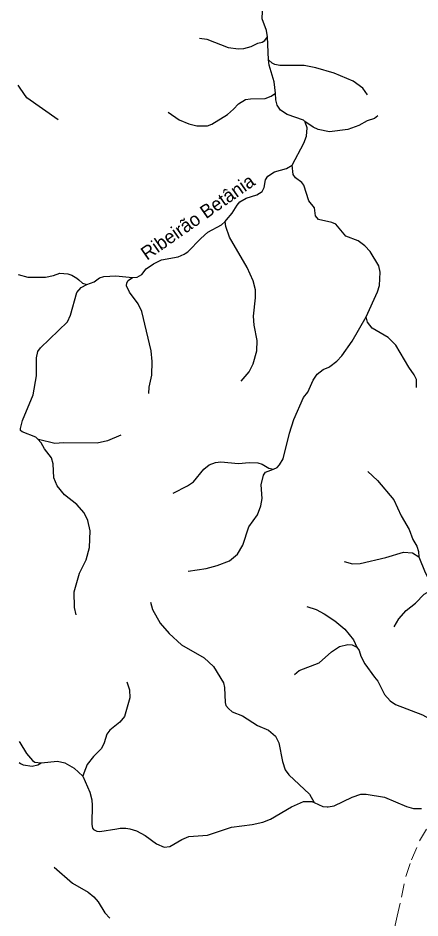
# Model space of a CAD drawing. Extents: x 473.9 to 500, y 7733.1 to 7760.8.
# Drawn here: x 473.9 to 476.88, y 7748.41 to 7755.08 of the extents above; entities that cross this region are included whole.
import ezdxf
from ezdxf.enums import TextEntityAlignment as Align

# ---------------------------------------------------------------- set-up
doc = ezdxf.new("R2010")
doc.units = 0
doc.header["$LTSCALE"] = 0.032
doc.linetypes.add('SHORT_DASHED', pattern=[2.7, 1.5, -1.2])
doc.layers.add('21', color=7, linetype='SHORT_DASHED', lineweight=13)
doc.layers.add('7', color=7, linetype='Continuous', lineweight=25)
doc.layers.add('61', color=7, linetype='Continuous')

msp = doc.modelspace()

# ---------------------------------------------------------------- linework, layer by layer
at = {"layer": '21'}
msp.add_lwpolyline([(476.688, 7748.3322), (476.7061, 7748.4194), (476.7376, 7748.5617), (476.7719, 7748.7144), (476.812, 7748.8386), (476.8731, 7748.9789), (476.9333, 7749.0811), (476.9689, 7749.1188), (477.0449, 7749.1653), (477.1611, 7749.2054), (477.4104, 7749.2751), (477.5096, 7749.3174), (477.554, 7749.3533), (477.5899, 7749.3913), (477.6275, 7749.4709)], dxfattribs=at)
at = {"layer": '7'}
msp.add_line((475.7531, 7754.7692), (475.7461, 7754.939), dxfattribs=at)
for points in [[(475.7461, 7754.939), (475.7396, 7754.9869), (475.7069, 7755.0721), (475.7082, 7755.1289), (475.6703, 7755.2102)], [(475.2436, 7754.9292), (475.2958, 7754.9229), (475.4549, 7754.8614), (475.5305, 7754.8493), (475.5716, 7754.8528), (475.6253, 7754.8675), (475.6747, 7754.8922), (475.7079, 7754.8999), (475.7267, 7754.9117), (475.7461, 7754.939)], [(475.8059, 7754.5227), (475.7959, 7754.6068), (475.7594, 7754.7284), (475.7531, 7754.7692)], [(476.488, 7754.5093), (476.4521, 7754.5578), (476.3815, 7754.6101), (476.239, 7754.6692), (476.105, 7754.7098), (476.0174, 7754.7273), (475.8385, 7754.7274), (475.8017, 7754.7336), (475.7806, 7754.7438), (475.7531, 7754.7692)], [(474.1951, 7754.3247), (473.964, 7754.488), (473.9141, 7754.5583), (473.8985, 7754.5803)], [(475.0106, 7754.3805), (475.0925, 7754.3229), (475.1646, 7754.294), (475.2231, 7754.2784), (475.3024, 7754.2798), (475.3348, 7754.2911), (475.4489, 7754.3627), (475.4952, 7754.4027), (475.5302, 7754.4424), (475.5829, 7754.4741), (475.6204, 7754.4804), (475.729, 7754.4826), (475.7744, 7754.4993), (475.8059, 7754.5227)], [(476.0222, 7754.3109), (476.013, 7754.3219), (475.8925, 7754.3625), (475.8421, 7754.3957), (475.8181, 7754.4336), (475.8088, 7754.4721), (475.8059, 7754.5227)], [(476.564, 7754.3546), (476.5382, 7754.3341), (476.4853, 7754.3168), (476.4233, 7754.2823), (476.341, 7754.252), (476.2048, 7754.2345), (476.1221, 7754.2517), (476.0852, 7754.2686), (476.0222, 7754.3109)], [(475.9288, 7753.987), (476.016, 7754.1513), (476.0343, 7754.2033), (476.0395, 7754.2655), (476.0264, 7754.306), (476.0222, 7754.3109)], [(475.4332, 7753.5703), (475.443, 7753.5824), (475.4834, 7753.6327), (475.5204, 7753.6925), (475.5425, 7753.7153), (475.5874, 7753.7437), (475.6665, 7753.7679), (475.7058, 7753.7925), (475.7205, 7753.8216), (475.7321, 7753.8802), (475.7499, 7753.9076), (475.7974, 7753.9384), (475.8879, 7753.9635), (475.9288, 7753.987)], [(476.4779, 7752.8624), (476.5616, 7753.0487), (476.5752, 7753.0969), (476.5815, 7753.1946), (476.5707, 7753.2415), (476.506, 7753.3486), (476.4672, 7753.389), (476.4174, 7753.4273), (476.3261, 7753.4618), (476.2527, 7753.5504), (476.2237, 7753.5633), (476.1233, 7753.5852), (476.1006, 7753.6129), (476.0938, 7753.6712), (476.0511, 7753.7229), (476.0147, 7753.839), (475.9993, 7753.8584), (475.953, 7753.8942), (475.9354, 7753.918), (475.9288, 7753.987)], [(474.7472, 7753.1562), (474.78, 7753.1585), (474.815, 7753.1782), (474.8483, 7753.2192), (474.9017, 7753.2571), (474.9617, 7753.2872), (475.0836, 7753.3086), (475.1293, 7753.3273), (475.1371, 7753.3326), (475.1574, 7753.3465), (475.252, 7753.4451), (475.3045, 7753.4907), (475.4048, 7753.5462), (475.4332, 7753.5703)], [(475.5511, 7752.3876), (475.6113, 7752.4549), (475.64, 7752.5152), (475.666, 7752.6113), (475.6707, 7752.6882), (475.6484, 7752.8012), (475.6428, 7752.8677), (475.6572, 7753.0039), (475.6572, 7753.0642), (475.6407, 7753.1308), (475.5953, 7753.2283), (475.4646, 7753.4544), (475.4367, 7753.5324), (475.4332, 7753.5703)], [(473.9006, 7753.1772), (473.9711, 7753.1568), (474.1027, 7753.1576), (474.1613, 7753.1691), (474.2083, 7753.1863), (474.2676, 7753.1815), (474.2968, 7753.1718), (474.3353, 7753.15), (474.3484, 7753.1385), (474.3768, 7753.1135), (474.408, 7753.1022)], [(474.408, 7753.1022), (474.4615, 7753.1221), (474.5031, 7753.1517), (474.5351, 7753.1615), (474.6226, 7753.168), (474.7472, 7753.1562)], [(474.8665, 7752.2962), (474.869, 7752.3416), (474.8906, 7752.4305), (474.8915, 7752.5314), (474.8834, 7752.6107), (474.8155, 7752.902), (474.789, 7752.96), (474.724, 7753.0458), (474.7024, 7753.0939), (474.7039, 7753.1146), (474.7144, 7753.1333), (474.7472, 7753.1562)], [(474.0454, 7751.9557), (474.0292, 7751.9725), (473.9296, 7752.0116), (473.918, 7752.0197), (473.9177, 7752.0363), (473.9323, 7752.0953), (474.0119, 7752.2855), (474.0359, 7752.4259), (474.0345, 7752.5587), (474.0446, 7752.6055), (474.0644, 7752.6344), (474.2652, 7752.8259), (474.2884, 7752.8765), (474.3352, 7753.0439), (474.3658, 7753.0822), (474.408, 7753.1022)], [(475.7901, 7751.7345), (475.8168, 7751.7471), (475.8358, 7751.7655), (475.8632, 7751.8105), (475.9099, 7752.002), (475.9415, 7752.1017), (476.0136, 7752.2643), (476.0446, 7752.3047), (476.0841, 7752.3936), (476.1142, 7752.4391), (476.1588, 7752.4723), (476.2008, 7752.4913), (476.2082, 7752.4946), (476.2595, 7752.5341), (476.2963, 7752.5733), (476.3739, 7752.6829), (476.4779, 7752.8624)], [(476.8506, 7752.3408), (476.8485, 7752.3982), (476.8324, 7752.4345), (476.7929, 7752.49), (476.6962, 7752.654), (476.6396, 7752.7092), (476.5205, 7752.7792), (476.486, 7752.824), (476.4779, 7752.8624)], [(474.6596, 7751.9852), (474.5618, 7751.945), (474.4858, 7751.927), (474.2363, 7751.9296), (474.1704, 7751.925), (474.0492, 7751.9548), (474.0454, 7751.9557)], [(474.3297, 7750.6537), (474.3158, 7750.7079), (474.3155, 7750.8248), (474.3531, 7750.9622), (474.4037, 7751.061), (474.4289, 7751.1537), (474.4328, 7751.2765), (474.4155, 7751.354), (474.3883, 7751.4106), (474.3345, 7751.471), (474.2421, 7751.5442), (474.1889, 7751.6116), (474.1632, 7751.6689), (474.1586, 7751.7739), (474.1474, 7751.8183), (474.094, 7751.8841), (474.0698, 7751.9305), (474.0454, 7751.9557)], [(475.0468, 7751.5549), (475.1549, 7751.6107), (475.1982, 7751.6401), (475.2736, 7751.7333), (475.3147, 7751.7656), (475.3615, 7751.7833), (475.4016, 7751.7896), (475.5317, 7751.776), (475.6092, 7751.784), (475.6739, 7751.7816), (475.707, 7751.77), (475.7555, 7751.7425), (475.7901, 7751.7345)], [(475.1584, 7750.9788), (475.2913, 7750.9973), (475.3736, 7751.0195), (475.4658, 7751.0546), (475.5236, 7751.1027), (475.5631, 7751.1717), (475.609, 7751.307), (475.6723, 7751.396), (475.6977, 7751.4631), (475.7069, 7751.5155), (475.6997, 7751.6187), (475.7166, 7751.6891), (475.7308, 7751.7108), (475.7901, 7751.7345)], [(476.4892, 7751.718), (476.5617, 7751.6491), (476.6826, 7751.5058), (476.7362, 7751.389), (476.7958, 7751.2858), (476.8235, 7751.2127), (476.852, 7751.162), (476.8653, 7751.1248), (476.8676, 7751.0851)], [(476.3135, 7751.0495), (476.3763, 7751.0311), (476.4321, 7751.0335), (476.6226, 7751.0786), (476.7542, 7751.1193), (476.8192, 7751.1139), (476.8676, 7751.0851)], [(476.8676, 7751.0851), (476.914, 7750.9677), (476.9479, 7750.9032), (476.9897, 7750.8554)], [(476.6842, 7750.5651), (476.7179, 7750.6238), (476.7738, 7750.6854), (476.8413, 7750.7418), (476.9068, 7750.8069), (476.9897, 7750.8554)], [(474.8789, 7750.7481), (474.8942, 7750.6937), (474.9511, 7750.5912), (475.0168, 7750.5146), (475.1094, 7750.4326), (475.2782, 7750.335), (475.3474, 7750.2705), (475.4194, 7750.1497), (475.4271, 7750.1164), (475.4327, 7750.0046), (475.4384, 7749.9822), (475.4562, 7749.9597), (475.4834, 7749.9358), (475.562, 7749.9045), (475.6714, 7749.8339), (475.7525, 7749.7988), (475.8065, 7749.7537), (475.8299, 7749.7039), (475.8569, 7749.5665), (475.8775, 7749.504), (475.9048, 7749.4677), (476.0564, 7749.3251), (476.0917, 7749.2639)], [(476.0369, 7750.7169), (476.1056, 7750.6927), (476.1659, 7750.6613), (476.2443, 7750.61), (476.318, 7750.5475), (476.3833, 7750.4686), (476.4075, 7750.4134)], [(475.9462, 7750.2128), (475.98, 7750.242), (476.129, 7750.2991), (476.2194, 7750.3787), (476.2801, 7750.4186), (476.3421, 7750.433), (476.3742, 7750.4307), (476.4075, 7750.4134)], [(476.4075, 7750.4134), (476.4239, 7750.3892), (476.4375, 7750.3474), (476.467, 7750.2904), (476.5392, 7750.1926), (476.5622, 7750.1615), (476.6132, 7750.0627), (476.6535, 7750.0157), (476.6933, 7749.9891), (476.8936, 7749.9129), (476.9385, 7749.889), (477.0156, 7749.8307), (477.0689, 7749.7713), (477.0708, 7749.7683), (477.1668, 7749.62), (477.2475, 7749.4731), (477.2754, 7749.4402), (477.3213, 7749.4148), (477.3441, 7749.4173), (477.3739, 7749.4339), (477.4269, 7749.4809), (477.4592, 7749.4997), (477.5049, 7749.5012)], [(474.7045, 7750.1572), (474.723, 7750.0979), (474.7262, 7750.0399), (474.6868, 7749.9003), (474.6535, 7749.8575), (474.5793, 7749.7993), (474.5556, 7749.7686), (474.536, 7749.7059), (474.5158, 7749.664), (474.4574, 7749.6045), (474.4105, 7749.5449), (474.3866, 7749.4808), (474.3785, 7749.4591)], [(473.9059, 7749.7157), (473.9108, 7749.7077), (473.9604, 7749.627), (474.005, 7749.5748), (474.0226, 7749.562), (474.069, 7749.556)], [(473.9061, 7749.5586), (473.9172, 7749.5523), (473.9361, 7749.5415), (474.0045, 7749.5318), (474.0463, 7749.5423), (474.069, 7749.556)], [(474.069, 7749.556), (474.1898, 7749.5688), (474.2457, 7749.5579), (474.3139, 7749.5184), (474.3785, 7749.4591)], [(474.3785, 7749.4591), (474.4294, 7749.3384), (474.4448, 7749.2817), (474.4459, 7749.2731), (474.4488, 7749.2502), (474.4449, 7749.0999), (474.4505, 7749.0712), (474.4587, 7749.0619), (474.4812, 7749.0503), (474.5045, 7749.0483), (474.6306, 7749.0678), (474.6551, 7749.0716), (474.6961, 7749.0732), (474.7278, 7749.0676), (474.7765, 7749.0521), (474.8401, 7749.0179), (474.9233, 7748.9574), (474.98, 7748.9326), (475.022, 7748.9365), (475.1109, 7748.9889), (475.1627, 7749.0115), (475.3025, 7749.0217), (475.4802, 7749.0797), (475.6322, 7749.0988), (475.7118, 7749.1172), (475.7688, 7749.1399), (475.9247, 7749.2302), (476.013, 7749.2692), (476.0754, 7749.2693), (476.0917, 7749.2639)], [(476.0917, 7749.2639), (476.1548, 7749.2331), (476.1876, 7749.2304), (476.1955, 7749.2315), (476.2407, 7749.2378), (476.3737, 7749.3028), (476.4385, 7749.3233), (476.478, 7749.3249), (476.6131, 7749.3014), (476.7746, 7749.2331), (476.8264, 7749.2174), (476.8878, 7749.218)], [(474.1664, 7748.7837), (474.3012, 7748.6642), (474.4178, 7748.5968), (474.4604, 7748.5629), (474.4932, 7748.5261), (474.541, 7748.4453), (474.5797, 7748.4041)]]:
    msp.add_lwpolyline(points, dxfattribs=at)

# ---------------------------------------------------------------- texts
at = {"layer": '61'}
msp.add_text('Ribeirão Betânia', height=0.1, rotation=35.02, dxfattribs=at).set_placement((475.2579, 7753.5628), align=Align.CENTER)

doc.saveas('drawing.dxf')
